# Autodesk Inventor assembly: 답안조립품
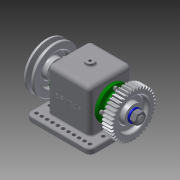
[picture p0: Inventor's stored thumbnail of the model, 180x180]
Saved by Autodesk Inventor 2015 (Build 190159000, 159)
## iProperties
Created: 2018-11
Part Number: 답안조립품
Document SubType Name: Assembly
Designer: now
Author: now
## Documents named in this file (13)
- C:\Users\now\Desktop\481108V1014\답안조립품.iam
- C:\Users\now\Desktop\481108V1014\V벨트풀리.ipt
- C:\Users\now\Desktop\481108V1014\너트 M12x1.25.ipt
- C:\Users\now\Desktop\481108V1014\베어링 6203.ipt
- C:\Users\now\Desktop\481108V1014\본체.ipt
- C:\Users\now\Desktop\481108V1014\볼트 M4.ipt
- C:\Users\now\Desktop\481108V1014\부시.ipt
- C:\Users\now\Desktop\481108V1014\스퍼기어.ipt
- C:\Users\now\Desktop\481108V1014\오일 실 26 38 8.ipt
- C:\Users\now\Desktop\481108V1014\와셔 12x24.ipt
- C:\Users\now\Desktop\481108V1014\축.ipt
- C:\Users\now\Desktop\481108V1014\커버.ipt
- C:\Users\now\Desktop\481108V1014\키 5x5x12.ipt
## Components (1 placed, 1 different names)
1. V벨트풀리:1 — 각도:4
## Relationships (1: Angle 1)
- 각도:4 [Angle]: V벨트풀리:1
